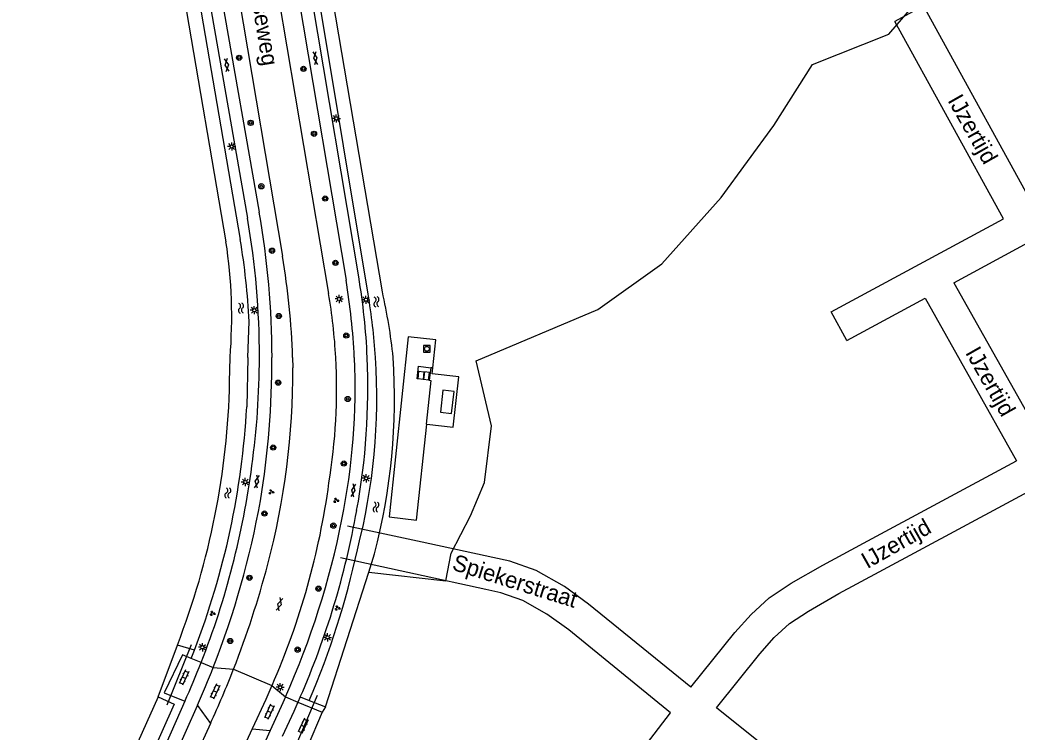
# Model space of a CAD drawing. Extents: x 136000 to 141000, y 400494 to 402006.
# Drawn here: x 137921 to 138073.4, y 401442.7 to 401551.6 of the extents above; entities that cross this region are included whole.
import ezdxf

# ---------------------------------------------------------------- set-up
doc = ezdxf.new("R2010")
doc.units = 0
for name, color, linetype in [('gg-afsc-erfafscheiding', 7, 'Continuous'), ('gg-anno-openbare ruimte label', 7, 'Continuous'), ('gg-bbg-lage trafo', 7, 'Continuous'), ('gg-knt-bronhoudergrens', 7, 'Continuous'), ('gg-knt-plantopografie kant verharding', 7, 'Continuous'), ('gg-knt-verharding', 7, 'Continuous'), ('gg-kntw-bovenkant insteek waterloop', 7, 'Continuous'), ('gg-kwrk-betonelement', 7, 'Continuous'), ('gg-kwrk-duiker nz buis', 7, 'Continuous'), ('gg-kwrk-luik', 7, 'Continuous'), ('gt-grn-groengrens', 7, 'Continuous'), ('gt-grn-weggrens', 7, 'Continuous'), ('gt-symb-boom', 7, 'Continuous'), ('gt-symb-gesloten verharding', 7, 'Continuous'), ('gt-symb-groenvak', 7, 'Continuous'), ('gt-symb-klinker verharding', 7, 'Continuous'), ('gt-symb-lichtmast', 7, 'Continuous'), ('gt-symb-rioolschacht', 7, 'Continuous'), ('gt-symb-watersymbool', 7, 'Continuous')]:
    doc.layers.add(name, color=color, linetype=linetype)

# ---------------------------------------------------------------- blocks, each defined once
blk = doc.blocks.new('gt0-GESVH1')
at = {"layer": 'gt-symb-gesloten verharding'}
for p, q in [((-0.99, -0.26), (0.01, 0.24)), ((0.01, -0.26), (-0.99, 0.24)), ((0.01, 0.24), (1.01, -0.26)), ((1.01, 0.24), (0.01, -0.26))]:
    blk.add_line(p, q, dxfattribs=at)
blk = doc.blocks.new('gt0-LMAST')
at = {"layer": 'gt-symb-lichtmast'}
for p, q in [((-0.18, 0.17), (-0.45, 0.44)), ((-0.01, 0.25), (-0.01, 0.62)), ((0.17, 0.17), (0.44, 0.44)), ((-0.26, 0), (-0.63, 0)), ((-0.18, -0.18), (-0.45, -0.45)), ((-0.01, -0.25), (-0.01, -0.63)), ((0.44, -0.45), (0.17, -0.18)), ((0.24, 0), (0.62, 0))]:
    blk.add_line(p, q, dxfattribs=at)
blk.add_circle((-0.01, 0), 0.25, dxfattribs=at)
blk = doc.blocks.new('gt0-BOOM')
at = {"layer": 'gt-symb-boom'}
for radius in [0.4, 0.2]:
    blk.add_circle((0, 0), radius, dxfattribs=at)
blk = doc.blocks.new('gt0-RS')
at = {"layer": 'gt-symb-rioolschacht'}
blk.add_lwpolyline([(-0.5, -0.5), (0.5, -0.5), (0.5, 0.5), (-0.5, 0.5)], close=True, dxfattribs=at)
blk.add_circle((0, 0), 0.375, dxfattribs=at)
blk = doc.blocks.new('gt0-KL1')
at = {"layer": 'gt-symb-klinker verharding'}
for p, q in [((-1.15, 0.3), (1.15, 0.3)), ((-1, -0.3), (-1, 0.3)), ((-0.5, 0.3), (-0.5, 0.45)), ((0, -0.3), (0, 0.3)), ((0.5, 0.3), (0.5, 0.45)), ((1, -0.3), (1, 0.3)), ((-1.15, -0.3), (1.15, -0.3)), ((-0.5, -0.45), (-0.5, -0.3)), ((0.5, -0.45), (0.5, -0.3))]:
    blk.add_line(p, q, dxfattribs=at)
blk = doc.blocks.new('gt0-GRVAK')
at = {"layer": 'gt-symb-groenvak'}
for p, q in [((-0.11, 0.19), (-0.23, 0.24)), ((-0.18, 0.15), (0.09, 0.15)), ((-0.09, 0.21), (-0.16, 0.32)), ((-0.05, 0.21), (-0.05, 0.39)), ((0, 0.21), (0.06, 0.32)), ((0.02, 0.19), (0.13, 0.24)), ((0.26, -0.05), (0.2, 0.06)), ((0.3, -0.05), (0.3, 0.13)), ((0.35, -0.05), (0.41, 0.06)), ((-0.24, -0.23), (-0.36, -0.18)), ((-0.32, -0.26), (-0.05, -0.26)), ((-0.23, -0.21), (-0.29, -0.09)), ((-0.18, -0.2), (-0.18, -0.02)), ((-0.14, -0.21), (-0.07, -0.09)), ((-0.12, -0.23), (0, -0.18)), ((0.24, -0.07), (0.12, -0.02)), ((0.17, -0.11), (0.44, -0.11)), ((0.37, -0.07), (0.49, -0.02))]:
    blk.add_line(p, q, dxfattribs=at)
blk = doc.blocks.new('gt0-WA')
at = {"layer": 'gt-symb-watersymbool'}
for centre, start, end in [((-0.32, 0.02), 28.0725, 151.9275), ((0.43, 0.42), 208.0725, 331.9275), ((-0.32, -0.43), 28.0725, 151.9275), ((0.43, -0.03), 208.0725, 331.9275)]:
    blk.add_arc(centre, 0.425, start, end, dxfattribs=at)

msp = doc.modelspace()

# ---------------------------------------------------------------- linework, layer by layer
at = {"layer": 'gg-afsc-erfafscheiding'}
for p, q in [((137942.08, 401448.09), (137945.03, 401456.02)), ((137967.69, 401446.57), (137967.14, 401445.76))]:
    msp.add_line(p, q, dxfattribs=at)
at = {"layer": 'gg-bbg-lage trafo'}
msp.add_lwpolyline([(137985.26, 401491.65), (137986.96, 401491.45), (137987.32, 401494.8), (137985.62, 401494.98), (137985.26, 401491.65)], dxfattribs=at)
at = {"layer": 'gg-knt-bronhoudergrens'}
msp.add_lwpolyline([(137974.28, 401467.17), (137986.05, 401465.84), (137986.89, 401470.08), (137989.86, 401475.79), (137991.97, 401480.87), (137993.03, 401489.55), (137990.7, 401499.5), (138009.33, 401507.33), (138019.07, 401514.32), (138028.17, 401524.48), (138036.21, 401535.48), (138042.14, 401544.8), (138053.78, 401549.45), (138061.82, 401558.77), (138067.3, 401561.51)], dxfattribs=at)
at = {"layer": 'gg-knt-plantopografie kant verharding'}
for p, q in [((138063.75, 401511.43), (138077.71, 401486.54)), ((138047.36, 401502.6), (138059.35, 401509.06)), ((138059.35, 401509.06), (138073.31, 401484.17))]:
    msp.add_line(p, q, dxfattribs=at)
for points in [[(138063.75, 401511.43), (138078.13, 401519.19), (138059.1, 401553.76), (138054.72, 401551.35)], [(138059.14, 401514.63), (138071.32, 401521.2), (138054.72, 401551.35)], [(138047.36, 401502.6), (138044.99, 401506.99), (138059.14, 401514.63)], [(138023.54, 401449.57), (138030.23, 401457.92), (138032.73, 401460.71), (138035.52, 401463.27), (138038.88, 401465.49), (138043.69, 401468.26), (138049.94, 401471.62), (138073.31, 401484.17)], [(138027.43, 401446.43), (138034.05, 401454.68), (138036.29, 401457.19), (138038.61, 401459.32), (138041.51, 401461.23), (138046.13, 401463.89), (138052.3, 401467.21), (138077.92, 401480.97)], [(138023.54, 401449.57), (138007.9, 401462.3), (138004.21, 401464.96), (137999.89, 401467.43), (137995.85, 401468.83), (137993.24, 401469.4), (137982.47, 401471.74), (137971.03, 401474.22)], [(138020.44, 401445.64), (138004.86, 401458.33), (138001.5, 401460.75), (137997.82, 401462.86), (137994.49, 401464), (137992.18, 401464.51), (137981.41, 401466.85), (137969.97, 401469.34)], [(138104.64, 401303.73), (138092.65, 401319.32), (138090.52, 401322.84), (138088.13, 401331.02), (138083.17, 401348.03), (138072.93, 401384.53), (138068.07, 401401.69), (138065.3, 401410.94), (138062.34, 401416.7), (138058.42, 401421.31), (138053.01, 401425.94), (138027.43, 401446.43)], [(138032.09, 401376.91), (138014.37, 401419.42), (138011.86, 401425.39), (138011.53, 401429.48), (138012.12, 401433.14), (138013.72, 401436.95), (138020.44, 401445.64)]]:
    msp.add_lwpolyline(points, dxfattribs=at)
at = {"layer": 'gg-knt-verharding'}
for p, q in [((137942.71, 401595.71), (137955.74, 401521.28)), ((137960.05, 401587.71), (137972.74, 401512.33)), ((137955.88, 401582.25), (137968.14, 401509.8)), ((137958.79, 401583.37), (137970.81, 401511.81)), ((137947.3, 401580.77), (137957.54, 401522.21)), ((137950.08, 401580.93), (137961.09, 401515.48)), ((137962.64, 401500), (137962.68, 401498.41)), ((137984.08, 401498.41), (137983.76, 401498.44)), ((137948.67, 401453.36), (137947.12, 401453.99)), ((137950.52, 401452.61), (137953.62, 401452.34)), ((137959.49, 401449.83), (137961.54, 401448.1)), ((137963.81, 401448.09), (137963.46, 401447.28)), ((137946.17, 401447.42), (137925.81, 401401.87)), ((137927.6, 401400.84), (137948.08, 401446.79)), ((137948.08, 401446.79), (137948.1, 401446.84)), ((137948.08, 401446.79), (137950.08, 401444.05)), ((137963.46, 401447.28), (137967.14, 401445.76)), ((137967.14, 401445.76), (137964.86, 401440.37)), ((137950.08, 401444.05), (137930.54, 401401.47)), ((137956.46, 401443.23), (137937.4, 401402.03)), ((137956.46, 401443.23), (137959.19, 401442.94)), ((137959.19, 401442.94), (137939.33, 401399.49))]:
    msp.add_line(p, q, dxfattribs=at)
for points in [[(137984.08, 401498.41), (137984.53, 401502.69), (137980.29, 401503.16), (137977.41, 401475.65), (137981.61, 401475.11), (137983.18, 401489.81)], [(137983.18, 401489.81), (137987.2, 401489.34), (137988.04, 401497.03), (137983.98, 401497.49), (137984.08, 401498.41)], [(137983.54, 401496.52), (137983.77, 401496.49), (137983.06, 401489.82), (137983.18, 401489.81)], [(137947.12, 401453.99), (137945.79, 401454.55), (137942.99, 401448.71), (137946.17, 401447.42)], [(137959.49, 401449.83), (137958.53, 401447.71), (137956.46, 401443.23)], [(137961.54, 401448.1), (137961.14, 401447.21), (137959.19, 401442.94)], [(137963.46, 401447.28), (137962.82, 401445.87), (137961.07, 401442.06)]]:
    msp.add_lwpolyline(points, dxfattribs=at)
for centre, radius, start, end in [((137835.26, 401500.19), 122.31, 359.9131, 9.9323), ((137827.67, 401499.61), 131.83, 0.1683, 9.8711), ((137849.17, 401496.47), 113.53, 1.7842, 9.6429), ((137872.43, 401495.28), 99.76, 2.7143, 9.541), ((137871.03, 401495.3), 103.13, 2.6121, 9.506), ((137881.39, 401495.13), 87.99, 3.1727, 9.5988), ((137835.53, 401500.17), 122.04, 352.1209, 359.9223), ((137827.79, 401499.61), 131.7, 350.5942, 0.1689), ((137881.6, 401495.15), 87.77, 350.5941, 3.167), ((137872.13, 401495.23), 100.07, 348.4608, 2.7298), ((137871.09, 401495.31), 103.06, 349.5363, 2.6102), ((137847.59, 401497.84), 115.09, 345.1705, 0.2803), ((137828.92, 401500.26), 128.61, 338.6122, 352.485), ((137853.41, 401496.34), 115.83, 336.3283, 352.2946), ((137823.2, 401502.38), 136.7, 338.6486, 349.7627), ((137846.04, 401499.78), 126.54, 335.8953, 348.8064), ((137846.65, 401499.11), 127.8, 336.4676, 349.8497), ((137817.55, 401505.57), 146.11, 338.6347, 345.2556), ((137829.02, 401500.21), 128.49, 335.7398, 338.6128), ((137823.53, 401502.23), 136.34, 336.0282, 338.6588), ((137818.03, 401505.34), 145.58, 335.0998, 338.6498)]:
    msp.add_arc(centre, radius, start, end, dxfattribs=at)
at = {"layer": 'gg-kntw-bovenkant insteek waterloop'}
for p, q in [((137974.19, 401509.68), (137958.87, 401602.11)), ((137938.45, 401599.32), (137952.46, 401517.69)), ((137955.78, 401500), (137955.99, 401505.48)), ((137953.02, 401496.29), (137953.08, 401500)), ((137955.78, 401500), (137955.64, 401492.45)), ((137974.28, 401467.17), (137975.17, 401469.98)), ((137967.69, 401446.57), (137974.28, 401467.17)), ((137947.62, 401455.24), (137945.03, 401456.02)), ((137965.18, 401447.56), (137967.69, 401446.57))]:
    msp.add_line(p, q, dxfattribs=at)
for points in [[(137976.37, 401510.05), (137966.12, 401570.37), (137960.88, 401602.69)], [(137938.45, 401599.32), (137940.65, 401599.49), (137954.63, 401518.06)], [(137942.08, 401448.09), (137923.4, 401406.42), (137920.96, 401400.84)], [(137942.08, 401448.09), (137944.55, 401446.98), (137928.37, 401410.75), (137925.86, 401405.32), (137923.46, 401399.83)]]:
    msp.add_lwpolyline(points, dxfattribs=at)
for centre, radius, start, end in [((137854.69, 401500.9), 101.4, 2.587, 9.7424), ((137877.31, 401506.21), 76.02, 355.3131, 8.6825), ((137882.31, 401493.98), 93.2, 3.706, 9.6979), ((137887.14, 401490.11), 91.43, 6.2126, 12.5973), ((137882.22, 401493.96), 93.3, 345.4984, 3.7094), ((137882.16, 401493.97), 96.06, 345.5363, 3.599), ((137834.19, 401498.95), 118.86, 338.8281, 358.7163), ((137834.25, 401499.13), 121.57, 338.8345, 356.8488), ((137850.03, 401497.08), 125.35, 336.7327, 347.8057)]:
    msp.add_arc(centre, radius, start, end, dxfattribs=at)
at = {"layer": 'gg-kwrk-betonelement'}
for p, q in [((137983.76, 401498.44), (137983.54, 401496.52)), ((137982.59, 401496.63), (137981.83, 401496.72)), ((137982.65, 401496.62), (137982.59, 401496.63)), ((137983.42, 401496.53), (137982.65, 401496.62)), ((137983.54, 401496.52), (137983.42, 401496.53))]:
    msp.add_line(p, q, dxfattribs=at)
msp.add_lwpolyline([(137981.83, 401496.72), (137981.7, 401496.73), (137981.9, 401498.66), (137983.76, 401498.44)], dxfattribs=at)
at = {"layer": 'gg-kwrk-duiker nz buis'}
for p, q in [((137947.11, 401456.06), (137943.42, 401446.82)), ((137966.41, 401448.29), (137962.46, 401439.11))]:
    msp.add_line(p, q, dxfattribs=at)
at = {"layer": 'gg-kwrk-luik'}
for points in [[(137981.83, 401496.72), (137981.96, 401497.88), (137982.73, 401497.79), (137982.59, 401496.63)], [(137983.42, 401496.53), (137983.55, 401497.69), (137982.79, 401497.78), (137982.65, 401496.62)]]:
    msp.add_lwpolyline(points, dxfattribs=at)
at = {"layer": 'gt-grn-groengrens'}
for p, q in [((137947.12, 401453.99), (137947.62, 401455.24)), ((137963.81, 401448.09), (137965.18, 401447.56))]:
    msp.add_line(p, q, dxfattribs=at)
msp.add_arc((138247.28, 401669.44), 207.58, 212.8664, 217.903, dxfattribs=at)
at = {"layer": 'gt-grn-weggrens'}
for p, q in [((137948.67, 401453.36), (137950.52, 401452.61)), ((137953.62, 401452.34), (137959.49, 401449.83)), ((137961.54, 401448.1), (137963.46, 401447.28))]:
    msp.add_line(p, q, dxfattribs=at)

# ---------------------------------------------------------------- block references
at = {"layer": 'gt-symb-boom'}
for p in [(137954.47, 401545.83), (137964.3, 401544.13), (137956.23, 401535.88), (137965.92, 401534.21), (137957.86, 401526.18), (137967.63, 401524.3), (137959.5, 401516.32), (137969.19, 401514.46), (137960.53, 401506.34), (137970.85, 401503.35), (137960.44, 401496.14), (137971.07, 401493.65), (137959.68, 401486.22), (137970.48, 401483.78), (137958.34, 401476.13), (137968.88, 401474.29), (137956.05, 401466.31), (137966.59, 401464.64), (137953.11, 401456.64), (137963.41, 401455.33)]:
    msp.add_blockref('gt0-BOOM', p, dxfattribs=at)
at = {"layer": 'gt-symb-gesloten verharding'}
for p, rotation in [((137952.58, 401544.73), -82.29934460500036), ((137966.12, 401545.79), -82.29934460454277), ((137957.2, 401481.03), -99.61302586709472), ((137971.94, 401479.69), -98.62422873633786), ((137960.62, 401462.26), 73.97589034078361)]:
    msp.add_blockref('gt0-GESVH1', p, dxfattribs=dict(at, rotation=rotation))
at = {"layer": 'gt-symb-groenvak'}
for p in [(137959.37, 401479.44), (137969.29, 401478.15), (137969.5, 401461.68), (137950.39, 401460.86)]:
    msp.add_blockref('gt0-GRVAK', p, dxfattribs=at)
at = {"layer": 'gt-symb-klinker verharding'}
for p, rotation in [((137946.04, 401451.06), -114.6951465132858), ((137950.78, 401448.93), -114.6951465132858), ((137959.08, 401445.82), -114.69514651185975), ((137964.25, 401443.65), -114.6951465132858)]:
    msp.add_blockref('gt0-KL1', p, dxfattribs=dict(at, rotation=rotation))
at = {"layer": 'gt-symb-lichtmast'}
for p in [(137969.33, 401536.55), (137953.34, 401532.26), (137969.76, 401508.95), (137973.85, 401508.82), (137956.79, 401507.23), (137955.42, 401480.95), (137973.9, 401481.52), (137967.99, 401457.2), (137948.87, 401455.69), (137960.75, 401449.58)]:
    msp.add_blockref('gt0-LMAST', p, dxfattribs=at)
at = {"layer": 'gt-symb-rioolschacht'}
msp.add_blockref('gt0-RS', (137983.18, 401501.32), dxfattribs=at)
at = {"layer": 'gt-symb-watersymbool'}
for p, rotation in [((137975.46, 401508.46), 98.97262661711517), ((137954.76, 401507.49), 98.97262661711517), ((137952.74, 401479.33), -92.2929004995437), ((137975.4, 401477.17), -90.28647651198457)]:
    msp.add_blockref('gt0-WA', p, dxfattribs=dict(at, rotation=rotation))

# ---------------------------------------------------------------- texts
at = {"layer": 'gg-anno-openbare ruimte label'}
for s, rotation, p in [('Udenhoutseweg', 279.4, (137954.09, 401568.29)), ('IJzertijd', 299.6, (138062.71, 401539.32)), ('IJzertijd', 299.6, (138065.42, 401500.74)), ('IJzertijd', 29.6, (138050.5, 401467.62)), ('Spiekerstraat', 342.6, (137986.89, 401467.58))]:
    msp.add_text(s, height=2.5, rotation=rotation, dxfattribs=at).set_placement(p)

doc.saveas('drawing.dxf')
